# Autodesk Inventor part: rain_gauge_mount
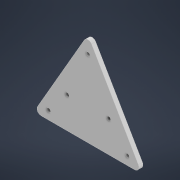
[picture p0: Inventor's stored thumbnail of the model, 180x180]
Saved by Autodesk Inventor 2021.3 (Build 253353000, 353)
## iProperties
Created: 2022-08
Part Number: rain_gauge_mount
Material: Generisch
Document SubType Name: Modeling
Designer: markus.rampp
Density: 1 g/cm^3
Appearance: Vorgabe
Author: markus.rampp
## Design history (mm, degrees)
sketch "Skizze1"
  geometry: L1 (-95, -54.848)-(95, -54.848); L2 (95, -54.848)-(0, 109.697); L3 (0, 109.697)-(-95, -54.848); L4 (130, -75.056)-(-130, -75.056); L5 (-130, -75.056)-(0, 150.111); L6 (0, 150.111)-(130, -75.056); L7 (0, 109.697)-(0, -121.798); C1 r 4.5 at (-95, -54.848); C2 r 4.5 at (95, -54.848); C3 r 4.5 at (0, 109.697); C4 r 4.5 at (50, 0); C5 r 4.5 at (-50, 0); A1 r 109.697 centre (0, 0) between (-95, -54.848) and (95, -54.848); A2 r 150.111 centre (0, 0) between (-130, -75.056) and (130, -75.056); 1 further point
  constraints: 14 end point, 7 centre point, 6 point on circle, 5 coincident, 2 horizontal, 2 horizontal alignment, 2 parallel, 1 perpendicular
  dimensions: "d1" = 60 deg angle of L2 L3; "d2" = 60 deg angle of L1 L3; "d3" = 190 distance of L1.start L1.end; "d4" = 260 distance of L4.start L4.end; "d5" = 9 diameter of C1; "d6" = 9 diameter of C2; "d7" = 9 diameter of C3; "d16" = 9 diameter of C4; "d17" = 9 diameter of C5; "d18" = 50 distance from line of L7 C5.centre; "d19" = 100 distance of C4.centre C5.centre
extrude "Extrusion1" new body sketch "Skizze1" distance "d8" = 10; taper "d9" = 0 deg
fillet "Rundung1" dims "d10" = 10
fillet "Rundung2" dims "d11" = 10
node "Volumenkörper1"
